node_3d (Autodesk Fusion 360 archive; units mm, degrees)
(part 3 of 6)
sketch "base" plane through (0, 0, 0) normal (0, 0, 1) x axis (1, 0, 0)
  line L1 (-45, 51.5) -> (45, 51.5)
  line L2 (-51.5, -45) -> (-51.5, 45)
  line L3 (45, -51.5) -> (-45, -51.5)
  line L4 (51.5, 45) -> (51.5, -45)
  line L5 (-51.5, -51.5) -> (51.5, 51.5)
  line L6 (51.5, -51.5) -> (-51.5, 51.5)
  line L7 (-20, 50) -> (-48, 50)
  line L8 (-18, 20) -> (-18, 48)
  line L9 (-48, 18) -> (-20, 18)
  line L10 (-50, 48) -> (-50, 20)
  line L11 (14, 50) -> (-14, 50)
  line L12 (16, 20) -> (16, 48)
  line L13 (-16, 48) -> (-16, 20)
  line L14 (-14, 18) -> (14, 18)
  line L15 (48, 50) -> (20, 50)
  line L16 (50, 20) -> (50, 48)
  line L17 (18, 48) -> (18, 20)
  line L18 (20, 18) -> (48, 18)
  line L19 (-20, 16) -> (-48, 16)
  line L20 (-18, -14) -> (-18, 14)
  line L21 (-50, 14) -> (-50, -14)
  line L22 (-48, -16) -> (-20, -16)
  line L23 (14, 16) -> (-14, 16)
  line L24 (16, -14) -> (16, 14)
  line L25 (-16, 14) -> (-16, -14)
  line L26 (-14, -16) -> (14, -16)
  line L27 (48, 16) -> (20, 16)
  line L28 (50, -14) -> (50, 14)
  line L29 (18, 14) -> (18, -14)
  line L30 (20, -16) -> (48, -16)
  line L31 (-20, -18) -> (-48, -18)
  line L32 (-18, -48) -> (-18, -20)
  line L33 (-50, -20) -> (-50, -48)
  line L34 (-48, -50) -> (-20, -50)
  line L35 (14, -18) -> (-14, -18)
  line L36 (16, -48) -> (16, -20)
  line L37 (-16, -20) -> (-16, -48)
  line L38 (-14, -50) -> (14, -50)
  line L39 (48, -18) -> (20, -18)
  line L40 (50, -48) -> (50, -20)
  line L41 (18, -20) -> (18, -48)
  line L42 (20, -50) -> (48, -50)
  line L43 (-33.38, 34.62) -> (-33.38, 36.12)
  line L44 (-33.38, 36.12) -> (-34.62, 36.12)
  line L45 (-34.62, 34.62) -> (-34.62, 36.12)
  line L46 (-34.62, 34.62) -> (-36.12, 34.62)
  line L47 (-36.12, 33.38) -> (-36.12, 34.62)
  line L48 (-34.62, 33.38) -> (-36.12, 33.38)
  line L49 (-34.62, 33.38) -> (-34.62, 31.88)
  line L50 (-33.38, 31.88) -> (-34.62, 31.88)
  line L51 (-33.38, 31.9) -> (-33.38, 31.88)
  line L52 (-33.38, 33.38) -> (-33.38, 31.9)
  line L53 (-33.38, 33.38) -> (-31.88, 33.38)
  line L54 (-31.88, 33.38) -> (-31.88, 34.62)
  line L55 (-33.38, 34.62) -> (-31.88, 34.62)
  line L56 (-50, 48) -> (-48, 50)
  line L57 (-18, 48) -> (-20, 50)
  line L58 (-50, 20) -> (-48, 18)
  line L59 (-18, 20) -> (-20, 18)
  line L60 (-16, 48) -> (-14, 50)
  line L61 (14, 18) -> (16, 20)
  line L62 (16, 48) -> (14, 50)
  line L63 (-16, 20) -> (-14, 18)
  line L64 (18, 48) -> (20, 50)
  line L65 (50, 20) -> (48, 18)
  line L66 (50, 48) -> (48, 50)
  line L67 (20, 18) -> (18, 20)
  line L68 (-50, 14) -> (-48, 16)
  line L69 (-50, -14) -> (-48, -16)
  line L70 (-20, -16) -> (-18, -14)
  line L71 (-18, 14) -> (-20, 16)
  line L72 (-14, 16) -> (-16, 14)
  line L73 (-16, -14) -> (-14, -16)
  line L74 (14, -16) -> (16, -14)
  line L75 (16, 14) -> (14, 16)
  line L76 (20, 16) -> (18, 14)
  line L77 (48, -16) -> (50, -14)
  line L78 (50, 14) -> (48, 16)
  line L79 (18, -14) -> (20, -16)
  line L80 (-50, -20) -> (-48, -18)
  line L81 (-50, -48) -> (-48, -50)
  line L82 (-20, -50) -> (-18, -48)
  line L83 (-18, -20) -> (-20, -18)
  line L84 (-14, -18) -> (-16, -20)
  line L85 (16, -48) -> (14, -50)
  line L86 (16, -20) -> (14, -18)
  line L87 (-16, -48) -> (-14, -50)
  line L88 (18, -48) -> (20, -50)
  line L89 (50, -48) -> (48, -50)
  line L90 (50, -20) -> (48, -18)
  line L91 (18, -20) -> (20, -18)
  line L92 (0.62, 34.62) -> (0.62, 36.12)
  line L93 (0.62, 36.12) -> (-0.62, 36.12)
  line L94 (-0.62, 34.62) -> (-0.62, 36.12)
  line L95 (-0.62, 34.62) -> (-2.12, 34.62)
  line L96 (-2.12, 33.38) -> (-2.12, 34.62)
  line L97 (-0.62, 33.38) -> (-2.12, 33.38)
  line L98 (-0.62, 33.38) -> (-0.62, 31.88)
  line L99 (0.62, 31.88) -> (-0.62, 31.88)
  line L100 (0.62, 31.9) -> (0.62, 31.88)
  line L101 (0.62, 33.38) -> (0.62, 31.9)
  line L102 (0.62, 33.38) -> (2.12, 33.38)
  line L103 (2.12, 33.38) -> (2.12, 34.62)
  line L104 (0.62, 34.62) -> (2.12, 34.62)
  line L105 (-34.62, 0.62) -> (-36.12, 0.62)
  line L106 (-36.12, 0.62) -> (-36.12, -0.62)
  line L107 (-34.62, -0.62) -> (-36.12, -0.62)
  line L108 (-34.62, -0.62) -> (-34.62, -2.12)
  line L109 (-33.38, -2.12) -> (-34.62, -2.12)
  line L110 (-33.38, -0.62) -> (-33.38, -2.12)
  line L111 (-33.38, -0.62) -> (-31.88, -0.62)
  line L112 (-31.88, 0.62) -> (-31.88, -0.62)
  line L113 (-33.38, 0.62) -> (-31.88, 0.62)
  line L114 (-33.38, 0.62) -> (-33.38, 2.1)
  line L115 (-33.38, 2.1) -> (-33.38, 2.12)
  line L116 (-33.38, 2.12) -> (-34.62, 2.12)
  line L117 (-34.62, 0.62) -> (-34.62, 2.12)
  line L118 (0, 16) -> (0, 18)
  line L119 (7.829, 17) -> (0, 17)
  line L120 (2.12, 0.62) -> (2.12, -0.62)
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  point P6 (0, 0)
  point P1 (0, 0)
  point P7 (-50, 50)
  point P8 (-18, 50)
  point P10 (-50, 18)
  point P9 (-18, 18)
  point P11 (-16, 50)
  point P13 (16, 18)
  point P12 (16, 50)
  point P14 (-16, 18)
  point P15 (18, 50)
  point P17 (50, 18)
  point P16 (50, 50)
  point P18 (18, 18)
  point P19 (-50, 16)
  point P22 (-50, -16)
  point P21 (-18, -16)
  point P20 (-18, 16)
  point P23 (-16, 16)
  point P26 (-16, -16)
  point P25 (16, -16)
  point P24 (16, 16)
  point P27 (18, 16)
  point P29 (50, -16)
  point P28 (50, 16)
  point P30 (18, -16)
  point P31 (-50, -18)
  point P34 (-50, -50)
  point P33 (-18, -50)
  point P32 (-18, -18)
  point P35 (-16, -18)
  point P37 (16, -50)
  point P36 (16, -18)
  point P38 (-16, -50)
  point P42 (18, -50)
  point P41 (50, -50)
  point P40 (50, -18)
  point P39 (18, -18)
  point P157 (0, 18)
  point P158 (0, 16)
  point P159 (0, 17)
  point P129 (-0.62, 33.38)
  point P165 (-0.62, 0.62)
  point P130 (0.62, 33.38)
  point P166 (0.62, 0.62)
  point P131 (0.62, 31.9)
  point P174 (0.62, 2.1)
  point P132 (0.62, 36.12)
  point P169 (0.62, -2.12)
  point P133 (2.12, 34.62)
  point P168 (2.12, -0.62)
  point P134 (-0.62, 31.88)
  point P170 (-0.62, 2.12)
  point P135 (2.12, 33.38)
  point P171 (2.12, 0.62)
  point P136 (-0.62, 36.12)
  point P172 (-0.62, -2.12)
  point P137 (-0.62, 34.62)
  point P163 (-0.62, -0.62)
  point P138 (0.62, 34.62)
  point P161 (0.62, -0.62)
  point P139 (-2.12, 34.62)
  point P162 (-2.12, -0.62)
  point P141 (-2.12, 33.38)
  point P164 (-2.12, 0.62)
  point P142 (0.62, 31.88)
  point P173 (0.62, 2.12)
  point P3 (-51.5, 51.5)
  point P2 (51.5, 51.5)
  point P4 (-51.5, -51.5)
  point P5 (51.5, -51.5)
  point P49 (-33.38, 36.12)
  point P56 (-34.62, 36.12)
  point P45 (-36.12, 33.38)
  point P46 (-36.12, 34.62)
  point P57 (-48, 50)
  point P58 (-50, 48)
  point P59 (-20, 50)
  point P60 (-18, 48)
  point P61 (-48, 18)
  point P62 (-50, 20)
  point P63 (-20, 18)
  point P64 (-18, 20)
  point P65 (-14, 50)
  point P66 (-16, 48)
  point P67 (16, 20)
  point P68 (14, 18)
  point P69 (14, 50)
  point P70 (16, 48)
  point P71 (-14, 18)
  point P72 (-16, 20)
  point P73 (20, 50)
  point P74 (18, 48)
  point P75 (48, 18)
  point P76 (50, 20)
  point P77 (48, 50)
  point P78 (50, 48)
  point P79 (18, 20)
  point P80 (20, 18)
  point P81 (-48, 16)
  point P82 (-50, 14)
  point P83 (-48, -16)
  point P84 (-50, -14)
  point P85 (-18, -14)
  point P86 (-20, -16)
  point P87 (-20, 16)
  point P88 (-18, 14)
  point P89 (-16, 14)
  point P90 (-14, 16)
  point P91 (-14, -16)
  point P92 (-16, -14)
  point P93 (16, -14)
  point P94 (14, -16)
  point P95 (14, 16)
  point P96 (16, 14)
  point P97 (18, 14)
  point P98 (20, 16)
  point P99 (50, -14)
  point P100 (48, -16)
  point P101 (48, 16)
  point P102 (50, 14)
  point P103 (20, -16)
  point P104 (18, -14)
  point P105 (-48, -18)
  point P106 (-50, -20)
  point P107 (-48, -50)
  point P108 (-50, -48)
  point P109 (-18, -48)
  point P110 (-20, -50)
  point P111 (-20, -18)
  point P112 (-18, -20)
  point P113 (-16, -20)
  point P114 (-14, -18)
  point P115 (14, -50)
  point P116 (16, -48)
  point P117 (14, -18)
  point P118 (16, -20)
  point P119 (-14, -50)
  point P120 (-16, -48)
  point P121 (20, -50)
  point P122 (18, -48)
  point P123 (48, -50)
  point P124 (50, -48)
  point P125 (48, -18)
  point P126 (50, -20)
  point P127 (20, -18)
  point P128 (18, -20)
  horizontal L1
  perpendicular L1 L2
  parallel L1 L3
  parallel L2 L4
  coincident L5 P6
  coincident L6 P6
  coincident P1 P6
  horizontal L7
  vertical L8
  horizontal L9
  vertical L10
  coincident L6 P7
  horizontal L44
  vertical L47
  perpendicular L46 L47
  perpendicular L47 L48
  perpendicular L48 L49
  perpendicular L53 L54
  perpendicular L45 L46
  perpendicular L43 L55
  perpendicular L50 L51
  perpendicular L50 L52
  coincident P7 L7
  coincident P7 L10
  coincident P8 L7
  coincident P8 L8
  coincident P10 L9
  coincident P10 L10
  coincident P9 L9
  coincident P9 L8
  coincident P11 L11
  coincident P11 L13
  coincident P13 L12
  coincident P13 L14
  coincident P12 L11
  coincident P12 L12
  coincident P14 L14
  coincident P14 L13
  coincident P15 L15
  coincident P15 L17
  coincident P17 L18
  coincident P17 L16
  coincident P16 L15
  coincident P16 L16
  coincident P18 L17
  coincident P18 L18
  coincident P19 L19
  coincident P19 L21
  coincident P22 L22
  coincident P22 L21
  coincident P21 L20
  coincident P21 L22
  coincident P20 L19
  coincident P20 L20
  coincident P23 L25
  coincident P23 L23
  coincident P26 L26
  coincident P26 L25
  coincident P25 L24
  coincident P25 L26
  coincident P24 L23
  coincident P24 L24
  coincident P27 L29
  coincident P27 L27
  coincident P29 L28
  coincident P29 L30
  coincident P28 L27
  coincident P28 L28
  coincident P30 L30
  coincident P30 L29
  coincident P31 L31
  coincident P31 L33
  coincident P34 L34
  coincident P34 L33
  coincident P33 L32
  coincident P33 L34
  coincident P32 L31
  coincident P32 L32
  coincident P35 L37
  coincident P35 L35
  coincident P37 L38
  coincident P37 L36
  coincident P36 L35
  coincident P36 L36
  coincident P38 L38
  coincident P38 L37
  coincident P42 L42
  coincident P42 L41
  coincident P41 L42
  coincident P41 L40
  coincident P40 L39
  coincident P40 L40
  coincident P39 L39
  coincident P39 L41
  horizontal L93
  vertical L96
  perpendicular L95 L96
  perpendicular L96 L97
  perpendicular L97 L98
  perpendicular L102 L103
  perpendicular L94 L95
  perpendicular L92 L104
  perpendicular L99 L100
  perpendicular L99 L101
  midpoint L14 P157
  midpoint L23 P158
  midpoint L118 P159
  perpendicular L118 L119
  symmetric P129 L119 P165
  symmetric P130 L119 P166
  symmetric P131 L119 P174
  symmetric P132 L119 P169
  symmetric P133 L119 P168
  symmetric P134 L119 P170
  symmetric P135 L119 P171
  symmetric P136 L119 P172
  symmetric P137 L119 P163
  symmetric P138 L119 P161
  symmetric P139 L119 P162
  symmetric P141 L119 P164
  symmetric P142 L119 P173
  coincident P3 L1
  coincident P3 L2
  coincident P2 L4
  coincident P2 L1
  coincident P4 L3
  coincident P4 L2
  coincident P5 L4
  coincident P5 L3
  dimension "d1" distance P2 P3 = 103
  dimension "d2" distance P3 P4 = 103
  dimension "d3" distance P7 P8 = 32
  dimension "d4" distance P7 P10 = 32
  dimension "d9" distance L1 L7 = 1.5
  dimension "d12" distance P49 P56 = 1.24
  dimension "d13" distance P45 P46 = 1.24
  dimension "d14" diameter = 5.5
  dimension "d16" distance P7 P57 = 2
  dimension "d17" distance P7 P58 = 2 (= "d16")
  dimension "d18" distance P8 P59 = 2
  dimension "d19" distance P8 P60 = 2 (= "d18")
  dimension "d20" distance P10 P61 = 2
  dimension "d21" distance P10 P62 = 2 (= "d20")
  dimension "d22" distance P9 P63 = 2
  dimension "d23" distance P9 P64 = 2 (= "d22")
  dimension "d24" distance P11 P65 = 2
  dimension "d25" distance P11 P66 = 2 (= "d24")
  dimension "d26" distance P13 P67 = 2
  dimension "d27" distance P13 P68 = 2 (= "d26")
  dimension "d28" distance P12 P69 = 2
  dimension "d29" distance P12 P70 = 2 (= "d28")
  dimension "d30" distance P14 P71 = 2
  dimension "d31" distance P14 P72 = 2 (= "d30")
  dimension "d32" distance P15 P73 = 2
  dimension "d33" distance P15 P74 = 2 (= "d32")
  dimension "d34" distance P17 P75 = 2
  dimension "d35" distance P17 P76 = 2 (= "d34")
  dimension "d36" distance P16 P77 = 2
  dimension "d37" distance P16 P78 = 2 (= "d36")
  dimension "d38" distance P18 P79 = 2
  dimension "d39" distance P18 P80 = 2 (= "d38")
  dimension "d40" distance P19 P81 = 2
  dimension "d41" distance P19 P82 = 2 (= "d40")
  dimension "d42" distance P22 P83 = 2
  dimension "d43" distance P22 P84 = 2 (= "d42")
  dimension "d44" distance P21 P85 = 2
  dimension "d45" distance P21 P86 = 2 (= "d44")
  dimension "d46" distance P20 P87 = 2
  dimension "d47" distance P20 P88 = 2 (= "d46")
  dimension "d48" distance P23 P89 = 2
  dimension "d49" distance P23 P90 = 2 (= "d48")
  dimension "d50" distance P26 P91 = 2
  dimension "d51" distance P26 P92 = 2 (= "d50")
  dimension "d52" distance P25 P93 = 2
  dimension "d53" distance P25 P94 = 2 (= "d52")
  dimension "d54" distance P24 P95 = 2
  dimension "d55" distance P24 P96 = 2 (= "d54")
  dimension "d56" distance P27 P97 = 2
  dimension "d57" distance P27 P98 = 2 (= "d56")
  dimension "d58" distance P29 P99 = 2
  dimension "d59" distance P29 P100 = 2 (= "d58")
  dimension "d60" distance P28 P101 = 2
  dimension "d61" distance P28 P102 = 2 (= "d60")
  dimension "d62" distance P30 P103 = 2
  dimension "d63" distance P30 P104 = 2 (= "d62")
  dimension "d64" distance P31 P105 = 2
  dimension "d65" distance P31 P106 = 2 (= "d64")
  dimension "d66" distance P34 P107 = 2
  dimension "d67" distance P34 P108 = 2 (= "d66")
  dimension "d68" distance P33 P109 = 2
  dimension "d69" distance P33 P110 = 2 (= "d68")
  dimension "d70" distance P32 P111 = 2
  dimension "d71" distance P32 P112 = 2 (= "d70")
  dimension "d72" distance P35 P113 = 2
  dimension "d73" distance P35 P114 = 2 (= "d72")
  dimension "d74" distance P37 P115 = 2
  dimension "d75" distance P37 P116 = 2 (= "d74")
  dimension "d76" distance P36 P117 = 2
  dimension "d77" distance P36 P118 = 2 (= "d76")
  dimension "d78" distance P38 P119 = 2
  dimension "d79" distance P38 P120 = 2 (= "d78")
  dimension "d80" distance P42 P121 = 2
  dimension "d81" distance P42 P122 = 2 (= "d80")
  dimension "d82" distance P41 P123 = 2
  dimension "d83" distance P41 P124 = 2 (= "d82")
  dimension "d84" distance P40 P125 = 2
  dimension "d85" distance P40 P126 = 2 (= "d84")
  dimension "d86" distance P39 P127 = 2
  dimension "d87" distance P39 P128 = 2 (= "d86")
  dimension "d92" distance P132 P136 = 1.24
  dimension "d93" distance P139 P141 = 1.24
  dimension "d94" diameter = 5.5
  dimension "d97" distance L8 L13 = 2
  dimension "d98" distance L1 L11 = 1.5
  dimension "d103" radius = 6.5
extrude "Extrude1" new body sketch "base" profile of L7 L8 L9 L10 along normal blind 10 taper -25
chamfer "Chamfer1" distance 2
shell "Shell1" innerThickness 2
extrude "Extrude2" sketch "base" blind -7
extrude "Extrude3" new body sketch "base" profile of L1 L2 L3 L4 L7 L8 L9 L10 L11 L12 L13 L14 L15 L16 L17 L18 L19 L20 L21 L22 L23 L24 L25 L26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 along normal blind 1.5
extrude "Extrude4" new body sketch "base" against normal blind 35
shell "Shell2" innerThickness 2
move "Move1"
base_feature "Base Feature1"
base_feature "Base Feature1"
base_feature "Base Feature1"
base_feature "Base Feature1"
copy_paste "CutPaste1"
copy_paste "CutPaste2"
copy_paste "CutPaste3"
copy_paste "CutPaste4"
copy_paste "CutPaste5"
copy_paste "CutPaste6"
copy_paste "CutPaste7"
copy_paste "CutPaste8"
copy_paste "CutPaste9"
copy_paste "CutPaste10"
copy_paste "CutPaste11"
copy_paste "CutPaste12"
copy_paste "CutPaste13"
copy_paste "CutPaste14"
move "Move2"
move "Move3" TranslateX 0 TranslateY 0 TranslateZ -5
offset_faces "OffsetFaces1" distance -10
position "Position1"
rectangular_pattern "R-Pattern1" uSpaceDistance -68 vSpaceDistance -68
fillet "Fillet1" radius 1
fillet "Fillet2" radius 5.5
sketch "Sketch3" plane through (0, 0, 0) normal (0, 1, 0) x axis (1, 0, 0)
  line L1 (-5.5764, 18) -> (4, 18)
  line L2 (-5.5764, 19.8) -> (-5.5764, 18)
  line L3 (4, 19.8) -> (-5.5764, 19.8)
  line L4 (4, 18) -> (4, 19.8)
  line L5 (-18, 18) -> (-11, 18)
  line L6 (-18, 20) -> (-18, 18)
  line L7 (-11, 20) -> (-18, 20)
  line L8 (-11, 18) -> (-11, 20)
  line L9 (-8.2523, 16.2329) -> (6.7477, 16.2329)
  line L10 (-8.2523, 21.2329) -> (-8.2523, 16.2329)
  line L11 (6.7477, 21.2329) -> (-8.2523, 21.2329)
  line L12 (6.7477, 16.2329) -> (6.7477, 21.2329)
  circle C1 centre (3.1, 18.9) radius 0.6598
  circle C2 centre (1.15, 18.9) radius 0.6598
  circle C3 centre (-0.8, 18.9) radius 0.6598
  circle C4 centre (-2.75, 18.9) radius 0.6598
  circle C5 centre (-4.7, 18.9) radius 0.6598
  circle C6 centre (-13.75, 18.9) radius 0.6598
  circle C7 centre (-15.7, 18.9) radius 0.6598
  point P2 (4, 18)
  point P5 (4, 19.8)
  point P10 (6.7477, 16.2329)
  point P11 (-8.2523, 16.2329)
  point P12 (-8.2523, 21.2329)
  horizontal L1
  vertical L2
  horizontal L3
  vertical L4
  horizontal L5
  vertical L6
  horizontal L7
  vertical L8
  horizontal L9
  vertical L10
  horizontal L11
  vertical L12
  dimension "d116" distance P2 P5 = 1.8
  dimension "d172" distance P10 P11 = 15
  dimension "d173" distance P11 P12 = 5
  dimension "d176" R-Pattern1-uDistance = -7.8
  dimension "d177" R-Pattern1-vDistance = 0
extrude "Extrude5" cut sketch "Sketch3" profile of L1 L2 L3 L4 distance 140
sketch "Sketch4" plane through (0, 0, 0) normal (1, 0, 0) x axis (0, 1, 0)
  line L1 (-5.0595, -19.2788) -> (4.9405, -19.2788)
  line L2 (-5.0595, -21.0788) -> (-5.0595, -19.2788)
  line L3 (4.9405, -21.0788) -> (-5.0595, -21.0788)
  line L4 (4.9405, -19.2788) -> (4.9405, -21.0788)
  line L5 (-7.4314, -17.7671) -> (-7.4314, -22.7671)
  line L6 (-7.4314, -22.7671) -> (7.5686, -22.7671)
  line L7 (7.5686, -17.7671) -> (-7.4314, -17.7671)
  line L8 (7.5686, -22.7671) -> (7.5686, -17.7671)
  circle C1 centre (-1.9546, -20.1) radius 0.6598
  circle C2 centre (-3.9046, -20.1) radius 0.6598
  circle C3 centre (-0.0046, -20.1) radius 0.6598
  circle C4 centre (3.8954, -20.1) radius 0.6598
  circle C5 centre (1.9454, -20.1) radius 0.6598
  point P2 (4.9405, -19.2788)
  point P3 (-5.0595, -19.2788)
  point P5 (4.9405, -21.0788)
  point P6 (7.5686, -22.7671)
  point P9 (-7.4314, -22.7671)
  point P8 (-7.4314, -17.7671)
  horizontal L1
  vertical L2
  horizontal L3
  vertical L4
  horizontal L6
  vertical L5
  horizontal L7
  vertical L8
  dimension "d119" distance P2 P3 = 10
  dimension "d120" distance P2 P5 = 1.8
  dimension "d191" distance P6 P9 = 15
  dimension "d192" distance P8 P9 = 5
  dimension "d195" R-Pattern2-uDistance = -7.8
  dimension "d196" R-Pattern2-vDistance = 0
extrude "Extrude6" cut sketch "Sketch4" profile of L1 L2 L3 L4 distance 80
extrude "Extrude7" cut sketch "Sketch3" profile of L5 L6 L7 L8 along normal blind 93
copy_paste_bodies "CopyPasteBodies1"
move "Move4"
component_from_bodies "Body->Comp1"
component_from_bodies "Body->Comp2"
component_from_bodies "Body->Comp3"
component_from_bodies "Body->Comp4"
component_from_bodies "Body->Comp5"
component_from_bodies "Body->Comp6"
component_from_bodies "Body->Comp7"
component_from_bodies "Body->Comp8"
component_from_bodies "Body->Comp9"
component_from_bodies "Body->Comp10"
component_from_bodies "Body->Comp11"
copy_paste "CopyPaste1"
copy_paste "CutPaste1"
copy_paste "CutPaste2"
copy_paste "CutPaste3"
copy_paste "CutPaste4"
copy_paste "CutPaste5"
copy_paste "CutPaste6"
copy_paste "CutPaste7"
copy_paste "CutPaste8"
copy_paste "CutPaste9"
copy_paste "CutPaste10"
copy_paste "CutPaste11"
copy_paste "CutPaste12"
copy_paste "CopyPaste2"
copy_paste "CopyPaste3"
copy_paste "CopyPaste4"
sketch "disp" plane through (0, 0, 0) normal (0, 0, 1) x axis (1, 0, 0)
  line L1 (-42.9946, 55.9203) -> (41.8028, 55.9203)
  line L2 (-52.9946, 85.9203) -> (-52.9946, 65.9203)
  line L3 (41.8028, 95.9203) -> (-42.9946, 95.9203)
  line L4 (51.8028, 65.9203) -> (51.8028, 85.9203)
  line L5 (-11.1116, 63.2101) -> (37.8409, 63.2101)
  line L6 (-11.1116, 88.566) -> (-11.1116, 63.2101)
  line L7 (37.8409, 88.566) -> (-11.1116, 88.566)
  line L8 (47.8409, 73.2101) -> (47.8409, 78.566)
  line L9 (-39.5811, 77.7884) -> (-32.2288, 83.2962)
  line L10 (-46.1857, 78.2652) -> (-46.5805, 78.7923)
  line L11 (-37.7806, 90.8091) -> (-45.1818, 85.2646)
  line L12 (-31.5193, 90.6528) -> (-31.0754, 90.1624)
  line L13 (-10.1116, 87.566) -> (-10.1116, 64.2101)
  line L14 (37.8409, 87.566) -> (-10.1116, 87.566)
  line L15 (46.8409, 73.2101) -> (46.8409, 78.566)
  line L16 (-10.1116, 64.2101) -> (37.8409, 64.2101)
  line L17 (-37.181, 90.0088) -> (-44.5822, 84.4643)
  line L18 (-40.1807, 78.5887) -> (-32.8284, 84.0965)
  circle C1 centre (-13.0133, 75.8881) radius 12.8019
  arc A1 centre (-34.7828, 86.8074) radius 5 clockwise from (-37.7806, 90.8091) to (-31.0754, 90.1624)
  arc A2 centre (-35.2266, 87.2979) radius 5 clockwise from (-31.5193, 90.6528) to (-32.2288, 83.2962)
  arc A3 centre (-42.5789, 81.7901) radius 5 clockwise from (-39.5811, 77.7884) to (-46.5805, 78.7923)
  arc A4 centre (-42.184, 81.2629) radius 5 clockwise from (-46.1857, 78.2652) to (-45.1818, 85.2646)
  arc A5 centre (-42.9946, 85.9203) radius 10 clockwise from (-52.9946, 85.9203) to (-42.9946, 95.9203)
  arc A6 centre (-42.9946, 65.9203) radius 10 clockwise from (-42.9946, 55.9203) to (-52.9946, 65.9203)
  arc A7 centre (41.8028, 65.9203) radius 10 clockwise from (51.8028, 65.9203) to (41.8028, 55.9203)
  arc A8 centre (41.8028, 85.9203) radius 10 clockwise from (41.8028, 95.9203) to (51.8028, 85.9203)
  arc A9 centre (37.8409, 78.566) radius 10 clockwise from (37.8409, 88.566) to (47.8409, 78.566)
  arc A10 centre (37.8409, 73.2101) radius 10 clockwise from (47.8409, 73.2101) to (37.8409, 63.2101)
  arc A11 centre (37.8409, 78.566) radius 9 clockwise from (37.8409, 87.566) to (46.8409, 78.566)
  arc A12 centre (37.8409, 73.2101) radius 9 clockwise from (46.8409, 73.2101) to (37.8409, 64.2101)
  circle C2 centre (-42.4, 81.5) radius 3.4655
  arc A13 centre (-34.7828, 86.8074) radius 4 clockwise from (-37.181, 90.0088) to (-32.049, 89.7274)
  arc A14 centre (-42.184, 81.2629) radius 4 clockwise from (-45.5719, 79.1364) to (-44.5822, 84.4643)
  arc A15 centre (-42.5789, 81.7901) radius 4 clockwise from (-40.1807, 78.5887) to (-45.5719, 79.1364)
  arc A16 centre (-35.2266, 87.2979) radius 4 clockwise from (-32.049, 89.7274) to (-32.8284, 84.0965)
  point P2 (51.8028, 55.9203)
  point P3 (51.8028, 95.9203)
  horizontal L1
  vertical L2
  horizontal L3
  vertical L4
  horizontal L5
  vertical L6
  horizontal L7
  vertical L8
  perpendicular L9 L10
  perpendicular L10 L11
  tangent L11 A1
  tangent L12 A1
  tangent L12 A2
  tangent L9 A2
  equal A1 A2
  tangent L9 A3
  tangent L10 A3
  equal A1 A3
  tangent L10 A4
  tangent L11 A4
  equal A1 A4
  tangent L3 A5
  tangent L2 A5
  tangent L2 A6
  tangent L1 A6
  equal A5 A6
  coincident P2 L1
  coincident P2 L4
  tangent L1 A7
  tangent L4 A7
  equal A5 A7
  coincident P3 L3
  coincident P3 L4
  tangent L3 A8
  tangent L4 A8
  equal A5 A8
  tangent L7 A9
  tangent L8 A9
  equal A5 A9
  tangent L8 A10
  tangent L5 A10
  equal A5 A10
  dimension "d125" distance P2 P3 = 40
  dimension "d129" radius A1 = 5
  dimension "d130" = 1
  dimension "d131" radius A5 = 10
  dimension "d154" = 1
extrude "Extrude8" sketch "disp" profile of L1 L2 L3 L4 L5 L6 L7 L8 C1 L9 L10 L11 L12 A1 A2 A3 A4 L14 L13 L15 L16 A5 A6 A7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 blind 25
shell "Shell3" innerThickness 2
extrude "Extrude9" sketch "disp" profile of L1 L2 L3 L4 L5 L6 L7 L8 C1 L9 L10 L11 L12 A1 A2 A3 A4 A5 A6 A7 A8 A9 A10 blind 2 from offset -3
extrude "Extrude10" sketch "disp" profile of L5 L6 L7 L8 C1 L14 L15 L16 A9 A11 A10 A12 blind 1
extrude "Extrude11" sketch "disp" profile of C1 L14 L15 L16 A11 A12 blind 1.5
extrude "Extrude12" sketch "disp" profile of L6 C1 L14 L13 L16 blind 7 taper -16
chamfer "Chamfer2" distance 1
fillet "Fillet3" radius 2.5
extrude "Extrude13" sketch "disp" profile of L9 L11 A1 A2 A3 A4 blind 0.6
extrude "Extrude14" sketch "disp" profile of C2 L17 A14 A16 A15 L18 A13 blind -0.5
fillet "Fillet4" radius 0.25
fillet "Fillet5" radius 0.25
extrude "Extrude15" sketch "disp" profile of C2 blind 1.8
fillet "Fillet6" radius 0.875
copy_paste_bodies "CopyPasteBodies2"
component_from_bodies "Body->Comp12"
component_from_bodies "Body->Comp13"
component_from_bodies "Body->Comp14"
component_from_bodies "Body->Comp15"
component_from_bodies "Body->Comp16"
component_from_bodies "Body->Comp17"
component_from_bodies "Body->Comp18"
copy_paste "CutPaste1"
copy_paste "CutPaste2"
copy_paste "CutPaste3"
copy_paste "CutPaste4"
copy_paste "CutPaste5"
copy_paste "CutPaste6"
copy_paste "CutPaste7"
scale "Scale1" ScaleFactor 0.9989
fillet "Fillet1" radius 5
fillet "Fillet2" radius 1
decal "Decal1"
position "Position2"
extrude "Extrude16" sketch "Sketch3" profile of C1 C2 C3 C4 C5 blind -4
fillet "Fillet7" radius 0.5
extrude "Extrude17" sketch "Sketch3" profile of L1 L2 L3 L4 L9 L10 L11 L12 C1 C2 C3 C4 C5 blind 2
combine "Combine1"
extrude "Extrude18" sketch "Sketch4" blind 2
extrude "Extrude19" sketch "Sketch4" profile of C1 C2 C3 C4 C5 blind 2
mirror "Mirror1" mirrorStitchTolerance 0.1
mirror "Mirror2" mirrorStitchTolerance 0.1
extrude "Extrude20" sketch "Sketch3" profile of C6 C7 blind 3
fillet "Fillet8" radius 0.5
extrude "Extrude21" sketch "Sketch3" profile of L5 L6 L7 L8 C6 C7 blind -2
sketch "Sketch6" plane through (0, 0, -33) normal (0, 0, 1) x axis (-1, 0, 0)
  line L1 (-51.5, -47) -> (-51.5, 47)
  line L2 (47, -51.5) -> (-47, -51.5)
  line L3 (51.5, 47) -> (51.5, -47)
  line L4 (-47, 51.5) -> (47, 51.5)
  line L5 (-1, -51.5) -> (-1, 52)
  line L6 (1, -51.5) -> (1, 52)
  line L7 (3, -51.5) -> (3, 52)
  line L8 (5, -51.5) -> (5, 52)
  line L9 (4.3519, 7) -> (-2.8215, 7)
  line L10 (7.3519, -3) -> (7.3519, 4)
  line L11 (-2.8215, -6) -> (4.3519, -6)
  line L12 (-5.8215, 4) -> (-5.8215, -3)
  arc A1 centre (-47, 47) radius 4.5 clockwise from (-51.5, 47) to (-47, 51.5)
  arc A2 centre (-47, -47) radius 4.5 clockwise from (-47, -51.5) to (-51.5, -47)
  arc A3 centre (47, -47) radius 4.5 clockwise from (51.5, -47) to (47, -51.5)
  arc A4 centre (47, 47) radius 4.5 clockwise from (47, 51.5) to (51.5, 47)
  arc A5 centre (-2.8215, 4) radius 3 clockwise from (-5.8215, 4) to (-2.8215, 7)
  arc A6 centre (-2.8215, -3) radius 3 clockwise from (-2.8215, -6) to (-5.8215, -3)
  arc A7 centre (4.3519, -3) radius 3 clockwise from (7.3519, -3) to (4.3519, -6)
  arc A8 centre (4.3519, 4) radius 3 clockwise from (4.3519, 7) to (7.3519, 4)
  horizontal L9
  vertical L10
  horizontal L11
  vertical L12
  tangent L9 A5
  tangent L12 A5
  tangent L12 A6
  tangent L11 A6
  equal A5 A6
  tangent L11 A7
  tangent L10 A7
  equal A5 A7
  tangent L10 A8
  tangent L9 A8
  equal A5 A8
  dimension "d256" radius A5 = 3
sketch "Sketch7" plane through (0, -51.5, 0) normal (0, 1, 0) x axis (-1, 0, 0)
  line L1 (-4, -18) -> (-4, -19.8)
  line L2 (5.5764, -18) -> (-4, -18)
  line L3 (5.5764, -19.8) -> (5.5764, -18)
  line L4 (-4, -19.8) -> (5.5764, -19.8)
  line L5 (-47, -11) -> (47, -11)
  line L6 (-47, -33) -> (-47, -11)
  line L7 (47, -33) -> (-47, -33)
  line L8 (47, -11) -> (47, -33)
  line L9 (-3, -19) -> (-3, -33)
  point P10 (-3, -33)
  coincident L7 P10
  perpendicular L7 L9
pipe "Pipe2" SectionSize 0.8 SectionThickness 0.2
rectangular_pattern "R-Pattern2" uSpaceDistance 8 vSpaceDistance 0
pipe "Pipe3" SectionSize 0.8 SectionThickness 0.2
rectangular_pattern "R-Pattern3" uSpaceDistance 8 vSpaceDistance 0
mirror "Mirror3" mirrorStitchTolerance 0.1
mirror "Mirror4" mirrorStitchTolerance 0.1
mirror "Mirror5" mirrorStitchTolerance 0.1
mirror "Mirror6" mirrorStitchTolerance 0.1
mirror "Mirror7" mirrorStitchTolerance 0.1
combine "Combine2"
combine "Combine3"
combine "Combine4"
combine "Combine5"
combine "Combine6"
copy_paste_bodies "CopyPasteBodies4"
move "Move6" TranslateX 59 TranslateY -50 TranslateZ 0
extrude "Extrude22" new body sketch "Sketch6" profile of L5 L6 L7 L8 L9 L10 L11 L12 A5 A6 A7 A8 along normal blind 1
move "Move7" TranslateX -0.5 TranslateY 3 TranslateZ 0
component_from_bodies "Body->Comp19"
component_from_bodies "Body->Comp20"
component_from_bodies "Body->Comp21"
component_from_bodies "Body->Comp22"
component_from_bodies "Body->Comp23"
component_from_bodies "Body->Comp24"
component_from_bodies "Body->Comp25"
component_from_bodies "Body->Comp26"
component_from_bodies "Body->Comp27"
component_from_bodies "Body->Comp28"
component_from_bodies "Body->Comp29"
component_from_bodies "Body->Comp30"
component_from_bodies "Body->Comp31"
component_from_bodies "Body->Comp32"
component_from_bodies "Body->Comp33"
component_from_bodies "Body->Comp34"
component_from_bodies "Body->Comp35"
component_from_bodies "Body->Comp36"
copy_paste "CutPaste1"
copy_paste "CutPaste2"
copy_paste "CutPaste3"
copy_paste "CutPaste4"
copy_paste "CutPaste5"
copy_paste "CutPaste6"
copy_paste "CutPaste7"
copy_paste "CutPaste8"
copy_paste "CutPaste9"
copy_paste "CutPaste10"
copy_paste "CutPaste11"
copy_paste "CutPaste12"
copy_paste "CutPaste13"
copy_paste "CutPaste14"
copy_paste "CutPaste15"
copy_paste "CutPaste16"
copy_paste "CutPaste17"
copy_paste "CutPaste18"
sketch "disp2" plane through (0, 0, 0) normal (0, 0, 1) x axis (1, 0, 0)
  line L1 (-42.9946, 55.9203) -> (41.8028, 55.9203)
  line L2 (51.8028, 65.9203) -> (51.8028, 85.9203)
  line L3 (41.8028, 95.9203) -> (-42.9946, 95.9203)
  line L4 (-52.9946, 85.9203) -> (-52.9946, 65.9203)
  line L5 (43.8964, 90.7214) -> (-27.5036, 90.7214)
  line L6 (43.8964, 59.7214) -> (43.8964, 90.7214)
  line L7 (-27.5036, 59.7214) -> (43.8964, 59.7214)
  line L8 (-27.5036, 90.7214) -> (-27.5036, 59.7214)
  line L9 (-31.1995, 67.1836) -> (-31.1995, 83.1836)
  line L10 (-46.1995, 83.1836) -> (-46.1995, 67.1836)
  line L11 (41.8028, 94.4203) -> (-42.9946, 94.4203)
  line L12 (-51.4946, 85.9203) -> (-51.4946, 65.9203)
  line L13 (-42.9946, 57.4203) -> (41.8028, 57.4203)
  line L14 (50.3028, 65.9203) -> (50.3028, 85.9203)
  line L15 (-26.5036, 60.7214) -> (42.8964, 60.7214)
  line L16 (-26.5036, 89.7214) -> (-26.5036, 60.7214)
  line L17 (42.8964, 89.7214) -> (-26.5036, 89.7214)
  line L18 (42.8964, 60.7214) -> (42.8964, 89.7214)
  line L19 (-31.6266, 67.1836) -> (-31.6266, 83.1836)
  line L20 (-45.7724, 83.1836) -> (-45.7724, 67.1836)
  arc A1 centre (-42.9946, 65.9203) radius 10 clockwise from (-42.9946, 55.9203) to (-52.9946, 65.9203)
  arc A2 centre (41.8028, 65.9203) radius 10 clockwise from (51.8028, 65.9203) to (41.8028, 55.9203)
  arc A3 centre (41.8028, 85.9203) radius 10 clockwise from (41.8028, 95.9203) to (51.8028, 85.9203)
  arc A4 centre (-42.9946, 85.9203) radius 10 clockwise from (-52.9946, 85.9203) to (-42.9946, 95.9203)
  arc A5 centre (-38.6995, 83.1836) radius 7.5 clockwise from (-46.1995, 83.1836) to (-38.6995, 90.6836)
  arc A6 centre (-38.6995, 83.1836) radius 7.5 clockwise from (-38.6995, 90.6836) to (-31.1995, 83.1836)
  arc A7 centre (-38.6995, 67.1836) radius 7.5 clockwise from (-38.6995, 59.6836) to (-46.1995, 67.1836)
  arc A8 centre (-38.6995, 67.1836) radius 7.5 clockwise from (-31.1995, 67.1836) to (-38.6995, 59.6836)
  circle C1 centre (-38.6995, 67.1836) radius 6.3189
  arc A9 centre (41.8028, 85.9203) radius 8.5 clockwise from (41.8028, 94.4203) to (50.3028, 85.9203)
  arc A10 centre (-42.9946, 85.9203) radius 8.5 clockwise from (-51.4946, 85.9203) to (-42.9946, 94.4203)
  arc A11 centre (-42.9946, 65.9203) radius 8.5 clockwise from (-42.9946, 57.4203) to (-51.4946, 65.9203)
  arc A12 centre (41.8028, 65.9203) radius 8.5 clockwise from (50.3028, 65.9203) to (41.8028, 57.4203)
  arc A13 centre (-38.6995, 67.1836) radius 7.0729 clockwise from (-38.6995, 60.1107) to (-45.7724, 67.1836)
  arc A14 centre (-38.6995, 67.1836) radius 7.0729 clockwise from (-31.6266, 67.1836) to (-38.6995, 60.1107)
  arc A15 centre (-38.6995, 83.1836) radius 7.0729 clockwise from (-38.6995, 90.2566) to (-31.6266, 83.1836)
  arc A16 centre (-38.6995, 83.1836) radius 7.0729 clockwise from (-45.7724, 83.1836) to (-38.6995, 90.2566)
  point P18 (-46.1995, 90.6836)
  point P19 (-31.1995, 90.6836)
  point P22 (-38.6995, 90.6836)
  point P24 (-38.6995, 90.6836)
  point P20 (-46.1995, 59.6836)
  point P28 (-38.6995, 59.6836)
  point P30 (-38.6995, 59.6836)
  point P14 (-27.5036, 90.7214)
  point P15 (43.8964, 90.7214)
  point P17 (-27.5036, 59.7214)
  horizontal L5
  vertical L6
  horizontal L7
  vertical L8
  vertical L9
  vertical L10
  coincident P18 L10
  tangent L10 A5
  coincident P19 L9
  tangent L9 A6
  equal A5 A6
  coincident P22 P24
  coincident P20 L10
  tangent L10 A7
  equal A5 A7
  tangent L9 A8
  equal A5 A8
  coincident P28 P30
  concentric A8 C1
  dimension "d262" distance P14 P15 = 71.4
  dimension "d263" distance P14 P17 = 31
  dimension "d264" distance P18 P19 = 15
  dimension "d265" distance P18 P20 = 31
  dimension "d266" radius A5 = 7.5
  dimension "d270" = 1.5
  dimension "d271" = 1
  dimension "d281" = -0.4271
extrude "Extrude23" sketch "disp2" profile of A1 L1 A2 L2 A3 L3 A4 L4 L5 L6 L7 L8 L9 L10 A5 A6 A7 A8 C1 blind 25
extrude "Extrude24" sketch "disp2" profile of L5 L6 L7 L8 L9 L10 A5 A6 A7 A8 C1 A10 L11 L14 A11 L12 A12 A9 L13 L17 L18 L15 L16 blind -2
extrude "Extrude25" sketch "disp2" profile of L9 L10 A5 A6 A7 A8 C1 blind 1.5
extrude "Extrude26" sketch "disp2" profile of L17 L18 L15 L16 blind 2.2
extrude "Extrude27" sketch "disp2" profile of C1 A15 A13 A14 L19 A16 L20 blind -1
extrude "Extrude28" sketch "disp2" profile of C1 blind 3
fillet "Fillet9" radius 5
fillet "Fillet10" radius 1
fillet "Fillet11" radius 0.75
fillet "Fillet12" radius 1.5
cylinder_primitive "CylinderPrimitive1" Height 5 Diameter 18
chamfer "Chamfer3" distance 1
fillet "Fillet13" radius 6.5
combine "Combine7"
component_from_bodies "Body->Comp37"
sketch "disp3" plane through (0, 0, 0) normal (0, 0, 1) x axis (1, 0, 0)
  line L1 (51.8028, 65.9203) -> (51.8028, 85.9203)
  line L2 (-42.9946, 55.9203) -> (41.8028, 55.9203)
  line L3 (41.8028, 95.9203) -> (-42.9946, 95.9203)
  line L4 (-52.9946, 85.9203) -> (-52.9946, 65.9203)
  line L5 (34.1206, 79.9621) -> (12.1206, 79.9621)
  line L6 (34.1206, 74.4621) -> (34.1206, 79.9621)
  line L7 (12.1206, 74.4621) -> (34.1206, 74.4621)
  line L8 (12.1206, 79.9621) -> (12.1206, 74.4621)
  arc A1 centre (41.8028, 65.9203) radius 10 clockwise from (51.8028, 65.9203) to (41.8028, 55.9203)
  arc A2 centre (-42.9946, 65.9203) radius 10 clockwise from (-42.9946, 55.9203) to (-52.9946, 65.9203)
  arc A3 centre (-42.9946, 85.9203) radius 10 clockwise from (-52.9946, 85.9203) to (-42.9946, 95.9203)
  arc A4 centre (41.8028, 85.9203) radius 10 clockwise from (41.8028, 95.9203) to (51.8028, 85.9203)
  circle C1 centre (-13.141, 76.8765) radius 11.5032
  point P14 (12.1206, 79.9621)
  point P15 (34.1206, 79.9621)
  point P17 (12.1206, 74.4621)
  horizontal L5
  vertical L6
  horizontal L7
  vertical L8
  dimension "d301" distance P14 P15 = 22
  dimension "d302" distance P14 P17 = 5.5
sketch "disp4" plane through (0, 0, 0) normal (0, 0, 1) x axis (1, 0, 0)
  line L1 (-42.9946, 55.9203) -> (41.8028, 55.9203)
  line L2 (51.8028, 65.9203) -> (51.8028, 85.9203)
  line L3 (41.8028, 95.9203) -> (-42.9946, 95.9203)
  line L4 (-52.9946, 85.9203) -> (-52.9946, 65.9203)
  line L5 (34.0497, 86.4444) -> (-27.9503, 86.4444)
  line L6 (39.0497, 70.4444) -> (39.0497, 81.4444)
  line L7 (-26.9503, 65.4444) -> (34.0497, 65.4444)
  line L8 (-31.9503, 82.4444) -> (-31.9503, 70.4444)
  line L9 (41.8028, 94.9203) -> (-42.9946, 94.9203)
  line L10 (-51.9946, 85.9203) -> (-51.9946, 65.9203)
  line L11 (-42.9946, 56.9203) -> (41.8028, 56.9203)
  line L12 (50.8028, 65.9203) -> (50.8028, 85.9203)
  line L13 (-26.9503, 66.4444) -> (34.0497, 66.4444)
  line L14 (-30.9503, 82.4444) -> (-30.9503, 70.4444)
  line L15 (34.0497, 85.4444) -> (-27.9503, 85.4444)
  line L16 (38.0497, 70.4444) -> (38.0497, 81.4444)
  line L17 (-35.7905, 81.654) -> (-45.9777, 81.654)
  line L18 (-35.7905, 69.3649) -> (-35.7905, 81.654)
  line L19 (-45.9777, 69.3649) -> (-35.7905, 69.3649)
  line L20 (-45.9777, 81.654) -> (-45.9777, 69.3649)
  arc A1 centre (41.8028, 65.9203) radius 10 clockwise from (51.8028, 65.9203) to (41.8028, 55.9203)
  arc A2 centre (41.8028, 85.9203) radius 10 clockwise from (41.8028, 95.9203) to (51.8028, 85.9203)
  arc A3 centre (-42.9946, 85.9203) radius 10 clockwise from (-52.9946, 85.9203) to (-42.9946, 95.9203)
  arc A4 centre (-42.9946, 65.9203) radius 10 clockwise from (-42.9946, 55.9203) to (-52.9946, 65.9203)
  arc A5 centre (41.8028, 85.9203) radius 9 clockwise from (41.8028, 94.9203) to (50.8028, 85.9203)
  arc A6 centre (-42.9946, 85.9203) radius 9 clockwise from (-51.9946, 85.9203) to (-42.9946, 94.9203)
  arc A7 centre (-42.9946, 65.9203) radius 9 clockwise from (-42.9946, 56.9203) to (-51.9946, 65.9203)
  arc A8 centre (41.8028, 65.9203) radius 9 clockwise from (50.8028, 65.9203) to (41.8028, 56.9203)
  arc A9 centre (34.0497, 81.4444) radius 5 clockwise from (34.0497, 86.4444) to (39.0497, 81.4444)
  arc A10 centre (34.0497, 70.4444) radius 5 clockwise from (39.0497, 70.4444) to (34.0497, 65.4444)
  arc A11 centre (-26.9503, 70.4444) radius 5 clockwise from (-26.9503, 65.4444) to (-31.9503, 70.4444)
  arc A12 centre (-27.9503, 82.4444) radius 4 clockwise from (-31.9503, 82.4444) to (-27.9503, 86.4444)
  arc A13 centre (-26.9503, 70.4444) radius 4 clockwise from (-26.9503, 66.4444) to (-30.9503, 70.4444)
  arc A14 centre (-27.9503, 82.4444) radius 3 clockwise from (-30.9503, 82.4444) to (-27.9503, 85.4444)
  arc A15 centre (34.0497, 81.4444) radius 4 clockwise from (34.0497, 85.4444) to (38.0497, 81.4444)
  arc A16 centre (34.0497, 70.4444) radius 4 clockwise from (38.0497, 70.4444) to (34.0497, 66.4444)
  circle C1 centre (-40.8841, 81.654) radius 3.6827
  circle C2 centre (-40.8841, 81.654) radius 5.0936
  circle C3 centre (-40.8841, 69.3649) radius 5.0936
  point P15 (39.0497, 86.4444)
  point P16 (-31.9503, 65.4444)
  point P14 (-31.9503, 86.4444)
  point P58 (-35.7905, 69.3649)
  point P56 (-45.9777, 81.654)
  horizontal L5
  vertical L6
  horizontal L7
  vertical L8
  coincident P15 L5
  coincident P15 L6
  tangent L5 A9
  tangent L6 A9
  tangent L6 A10
  tangent L7 A10
  equal A9 A10
  coincident P16 L7
  coincident P16 L8
  tangent L7 A11
  tangent L8 A11
  equal A9 A11
  coincident P14 L5
  coincident P14 L8
  tangent L5 A12
  tangent L8 A12
  concentric C1 C2
  horizontal L17
  vertical L18
  horizontal L19
  vertical L20
  coincident C3 P58
  coincident C2 P56
  dimension "d303" distance P14 P15 = 71
  dimension "d304" distance P14 P16 = 21
  dimension "d305" = 1
  dimension "d306" = 1
  dimension "d307" radius A9 = 5
  dimension "d308" radius A12 = 4
extrude "Extrude29" sketch "disp4" profile of L1 A1 L2 A2 L3 A3 L4 A4 L5 L6 L7 L8 L13 L14 L15 L16 A8 A5 L12 L10 A6 L11 A7 L9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 blind 25
extrude "Extrude30" sketch "disp4" profile of L5 L6 L7 L8 L13 L14 L15 L16 A8 A5 L12 L10 A6 L11 A7 L9 A9 A15 A10 A16 A11 A13 A12 A14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 blind -2
extrude "Extrude31" sketch "disp4" profile of L5 L6 L7 L8 L13 L14 L15 L16 A9 A15 A10 A16 A11 A13 A12 A14 blind 1
extrude "Extrude33" sketch "disp4" profile of C1 C2 C3 L17 L18 L19 L20 blind 1
shell "Shell4" innerThickness 0.8
extrude "Extrude34" sketch "disp4" profile of C1 L17 blind 1.5
fillet "Fillet14" radius 1
sketch "Sketch12" plane through (0, 0, 0) normal (0, 1, 0) x axis (1, 0, 0)
  line L1 (-47, 29.5) -> (47, 29.5)
  line L2 (-47, 11) -> (-47, 29.5)
  line L3 (47, 11) -> (-47, 11)
  line L4 (47, 29.5) -> (47, 11)
  line L5 (47, 29.5) -> (47, 35)
  line L6 (-47, 35) -> (47, 35)
  line L7 (-47, 29.5) -> (-47, 35)
  line L8 (47, 29.5) -> (-47, 29.5)
  line L9 (47.92, 18.835) -> (47.92, 17.325)
  line L10 (-47.08, 18.835) -> (47.92, 18.835)
  line L11 (-47.08, 17.325) -> (-47.08, 18.835)
  line L12 (47.92, 17.325) -> (-47.08, 17.325)
  line L13 (-20.0561, -1.2557) -> (9.9439, -1.2557)
  line L14 (-20.0561, 8.7443) -> (-20.0561, -1.2557)
  line L15 (9.9439, 8.7443) -> (-20.0561, 8.7443)
  line L16 (9.9439, -1.2557) -> (9.9439, 8.7443)
  line L17 (-20.0561, 3.7443) -> (9.9439, 3.7443)
  line L18 (-20.0561, 4.4943) -> (9.9439, 4.4943)
  line L19 (-20.0561, 2.9943) -> (9.9439, 2.9943)
  line L20 (5.9439, 2.9943) -> (5.9439, 4.4943)
  line L21 (-5.0561, 8.7443) -> (-5.0561, -1.2557)
  line L22 (-16.0561, 2.9943) -> (-16.0561, 4.4943)
  point P18 (9.9439, 3.7443)
  point P19 (-20.0561, 3.7443)
  point P24 (5.9439, 4.4943)
  point P25 (5.9439, 2.9943)
  point P26 (-5.0561, -1.2557)
  point P27 (-5.0561, 8.7443)
  point P28 (-16.0561, 4.4943)
  point P29 (-16.0561, 2.9943)
  point P14 (9.9439, -1.2557)
  point P15 (-20.0561, -1.2557)
  point P17 (9.9439, 8.7443)
  horizontal L13
  vertical L14
  horizontal L15
  vertical L16
  midpoint L16 P18
  midpoint L14 P19
  coincident L18 P24
  coincident L19 P25
  perpendicular L19 L20
  midpoint L13 P26
  midpoint L15 P27
  symmetric P24 L21 P28
  symmetric P25 L21 P29
  dimension "d335" distance P14 P15 = 30
  dimension "d336" distance P14 P17 = 10
  dimension "d337" = 0.75 (= "( 1.5 / 2 ) * 1 mm")
  dimension "d338" = -0.75 (= "( -1.5 / 2 ) * 1 mm")
  dimension "d339" distance L16 L20 = 4
extrude "Extrude35" new body sketch "Sketch12" profile of L13 L14 L15 L16 L17 L18 L19 L20 L21 L22 along normal blind 1.51
work_plane "WorkPlane1" AlongDistance 0
sketch "Sketch13" plane through (0, 0, -4.4943) normal (0, 0, 1) x axis (1, 0, 0)
  line L1 (-20.0561, 1.51) -> (-20.0561, 0)
  line L2 (9.9439, 0) -> (-20.0561, 0)
  line L3 (9.9439, 1.51) -> (9.9439, 0)
  line L4 (9.9439, 0) -> (5.9439, 0)
  line L5 (9.9439, 1.51) -> (9.9439, 0)
  line L6 (5.9439, 1.51) -> (9.9439, 1.51)
  line L7 (5.9439, 0) -> (5.9439, 1.51)
  line L8 (-16.0561, 0) -> (-20.0561, 0)
  line L9 (-16.0561, 1.51) -> (-16.0561, 0)
  line L10 (-20.0561, 1.51) -> (-16.0561, 1.51)
  line L11 (12.9439, -8.49) -> (12.9439, 1.51)
  line L12 (-23.0561, -8.49) -> (12.9439, -8.49)
  line L13 (-23.0561, 1.51) -> (-23.0561, -8.49)
  line L14 (-16.0561, 1.51) -> (-23.0561, 1.51)
  line L15 (12.9439, 1.51) -> (5.9439, 1.51)
  point P14 (-23.0561, 1.51)
  point P15 (12.9439, 1.51)
  point P17 (-23.0561, -8.49)
  horizontal L14
  vertical L11
  horizontal L12
  vertical L13
  collinear L14 L15
  dimension "d343" distance P14 P15 = 36
  dimension "d344" distance P14 P17 = 10
  dimension "d345" distance L1 L13 = 3
extrude "Extrude36" new body sketch "Sketch13" profile of L1 L2 L3 L4 L5 L6 L7 L8 L9 L10 L15 L11 L12 L13 along normal blind 1.5
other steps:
base_feature "Base Feature1"
base_feature "Base Feature1"
base_feature "Base Feature1"
base_feature "Base Feature1"
base_feature "Base Feature1"
base_feature "Base Feature1"
base_feature "Base Feature1"
base_feature "Base Feature1"
base_feature "Base Feature1"
base_feature "Base Feature1"
base_feature "Base Feature1"
base_feature "Base Feature1"
base_feature "Base Feature1"
base_feature "Base Feature1"
base_feature "Base Feature1"
base_feature "Base Feature1"
base_feature "Base Feature1"
base_feature "Base Feature1"
base_feature "Base Feature1"
base_feature "Base Feature1"
base_feature "Base Feature1"
base_feature "Base Feature1"
base_feature "Base Feature1"
base_feature "Base Feature1"
base_feature "Base Feature1"
base_feature "Base Feature1"
base_feature "Base Feature1"
base_feature "Base Feature1"
base_feature "Base Feature1"
base_feature "Base Feature1"
base_feature "Base Feature1"
base_feature "Base Feature1"
base_feature "Base Feature1"
base_feature "Base Feature1"
base_feature "Base Feature1"
base_feature "Base Feature1"
base_feature "Base Feature1"
base_feature "Base Feature1"
base_feature "Base Feature2"
base_feature "Base Feature4"
create_component "CreateComponent4"
create_component "CreateComponent6"
create_component "CreateComponent7"
create_component "CreateComponent8"
create_component "CreateComponent9"
remove_instance "RemoveInstance1"
remove_instance "RemoveInstance2"
remove_instance "RemoveInstance3"
remove_instance "RemoveInstance4"
remove_instance "RemoveInstance5"
remove_instance "RemoveInstance6"
remove_instance "RemoveInstance7"
remove_instance "RemoveInstance8"
remove_instance "RemoveInstance9"
remove_instance "RemoveInstance10"
remove_instance "RemoveInstance11"
remove_instance "RemoveInstance12"
remove_instance "RemoveInstance13"
remove_instance "RemoveInstance14"
create_component "CreateComponent1"
create_component "CreateComponent2"
remove_body "RemoveBody1"
create_component "CreateComponent3"
remove_body "RemoveBody2"
create_component "CreateComponent4"
remove_body "RemoveBody3"
create_component "CreateComponent5"
remove_body "RemoveBody4"
create_component "CreateComponent6"
remove_body "RemoveBody5"
create_component "CreateComponent7"
remove_body "RemoveBody6"
create_component "CreateComponent8"
remove_body "RemoveBody7"
create_component "CreateComponent9"
remove_body "RemoveBody8"
create_component "CreateComponent10"
remove_body "RemoveBody9"
create_component "CreateComponent11"
remove_body "RemoveBody10"
create_component "CreateComponent12"
remove_body "RemoveBody11"
create_component "CreateComponent13"
remove_instance "RemoveInstance1"
remove_instance "RemoveInstance2"
remove_instance "RemoveInstance3"
remove_instance "RemoveInstance4"
remove_instance "RemoveInstance5"
remove_instance "RemoveInstance6"
remove_instance "RemoveInstance7"
remove_instance "RemoveInstance8"
remove_instance "RemoveInstance9"
remove_instance "RemoveInstance10"
remove_instance "RemoveInstance11"
remove_instance "RemoveInstance12"
create_component "CreateComponent14"
remove_body "RemoveBody12"
create_component "CreateComponent15"
remove_body "RemoveBody13"
create_component "CreateComponent16"
remove_body "RemoveBody14"
create_component "CreateComponent17"
remove_body "RemoveBody15"
create_component "CreateComponent18"
remove_body "RemoveBody16"
create_component "CreateComponent19"
remove_body "RemoveBody17"
create_component "CreateComponent20"
remove_body "RemoveBody18"
create_component "CreateComponent21"
remove_instance "RemoveInstance13"
remove_instance "RemoveInstance14"
remove_instance "RemoveInstance15"
remove_instance "RemoveInstance16"
remove_instance "RemoveInstance17"
remove_instance "RemoveInstance18"
remove_instance "RemoveInstance19"
create_component "CreateComponent22"
remove_body "RemoveBody19"
create_component "CreateComponent23"
remove_body "RemoveBody20"
create_component "CreateComponent24"
remove_body "RemoveBody21"
create_component "CreateComponent25"
remove_body "RemoveBody22"
create_component "CreateComponent26"
remove_body "RemoveBody23"
create_component "CreateComponent27"
remove_body "RemoveBody24"
create_component "CreateComponent28"
remove_body "RemoveBody25"
create_component "CreateComponent29"
remove_body "RemoveBody26"
create_component "CreateComponent30"
remove_body "RemoveBody27"
create_component "CreateComponent31"
remove_body "RemoveBody28"
create_component "CreateComponent32"
remove_body "RemoveBody29"
create_component "CreateComponent33"
remove_body "RemoveBody30"
create_component "CreateComponent34"
remove_body "RemoveBody31"
create_component "CreateComponent35"
remove_body "RemoveBody32"
create_component "CreateComponent36"
remove_body "RemoveBody33"
create_component "CreateComponent37"
remove_body "RemoveBody34"
create_component "CreateComponent38"
remove_body "RemoveBody35"
create_component "CreateComponent39"
remove_body "RemoveBody36"
create_component "CreateComponent40"
remove_instance "RemoveInstance20"
remove_instance "RemoveInstance21"
remove_instance "RemoveInstance22"
remove_instance "RemoveInstance23"
remove_instance "RemoveInstance24"
remove_instance "RemoveInstance25"
remove_instance "RemoveInstance26"
remove_instance "RemoveInstance27"
remove_instance "RemoveInstance28"
remove_instance "RemoveInstance29"
remove_instance "RemoveInstance30"
remove_instance "RemoveInstance31"
remove_instance "RemoveInstance32"
remove_instance "RemoveInstance33"
remove_instance "RemoveInstance34"
remove_instance "RemoveInstance35"
remove_instance "RemoveInstance36"
remove_instance "RemoveInstance37"
create_component "CreateComponent41"
remove_body "RemoveBody37"

design "button" references "PCB_forkeypad", "mockup_design2"
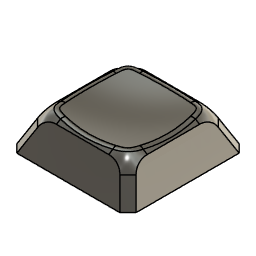
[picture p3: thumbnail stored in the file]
description: Part Number
part number: D_SOD-123
description: KiCad electronic assembly
part number: PCB_forkeypad1 1
part number: PCB_forkeypad1_PCB
part number: COM-13834
part number: PCB_forkeypad1_pad
sketch "Sketch1" plane through (0, 0, 0) normal (0, 0, 1) x axis (1, 0, 0)
  line L1 (10, 25) -> (-10, 25)
  line L2 (10, -25) -> (10, 25)
  line L3 (-10, -25) -> (10, -25)
  line L4 (-10, 25) -> (-10, -25)
  line L5 (10, -25) -> (-10, 25)
  line L6 (-10, -25) -> (10, 25)
  line L7 (0, 25) -> (0, -25)
  line L8 (10, 0) -> (0, 0)
  circle C1 centre (0, 14.6633) radius 5.1
  circle C2 centre (0, -14.6633) radius 5.1
  circle C3 centre (0, -14.6633) radius 0.5
  circle C4 centre (0, 14.6633) radius 0.5
  point P6 (0, 0)
  point P1 (0, 0)
  point P7 (0, -25)
  point P8 (0, 25)
  point P9 (0, 14.6633)
  point P10 (0, 0)
  point P11 (10, 0)
  point P4 (10, -25)
  point P5 (-10, -25)
  point P3 (10, 25)
  horizontal L1
  perpendicular L1 L2
  parallel L1 L3
  parallel L2 L4
  coincident L5 P6
  coincident L6 P6
  coincident P1 P6
  midpoint L3 P7
  midpoint L1 P8
  coincident L7 P9
  coincident P1 P10
  midpoint L2 P11
  symmetric C1 L8 C2
  concentric C2 C3
  concentric C1 C4
  dimension "d1" distance P4 P5 = 20
  dimension "d2" distance P3 P4 = 50
  dimension "d16" diameter C1 = 10.2
  dimension "d21" diameter C3 = 1
  dimension "d22" diameter C4 = 1
extrude "Extrude1" new body sketch "Sketch1" profile of L1 L2 L3 L4 L7 against normal blind 5
extrude "Extrude5" cut sketch "Sketch1" profile of L7 C1 against normal blind 4.5
extrude "Extrude6" cut sketch "Sketch1" profile of L7 C2 against normal blind 4.8
sketch "Sketch1" plane through (0, 0, 0) normal (0, 0, 1) x axis (1, 0, 0)
external_derived "ExternalDerived1"
derived_instance "DerivedInstance1"
derived_instance "DerivedInstance1"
